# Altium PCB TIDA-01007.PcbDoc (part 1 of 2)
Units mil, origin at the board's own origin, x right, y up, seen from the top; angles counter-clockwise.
Board outline 4950 x 3450 mil, 2 copper layers (Top Layer, Bottom Layer), stack 62 mil thick; 82 components, 45 nets, 235 pads, 1732 vias.
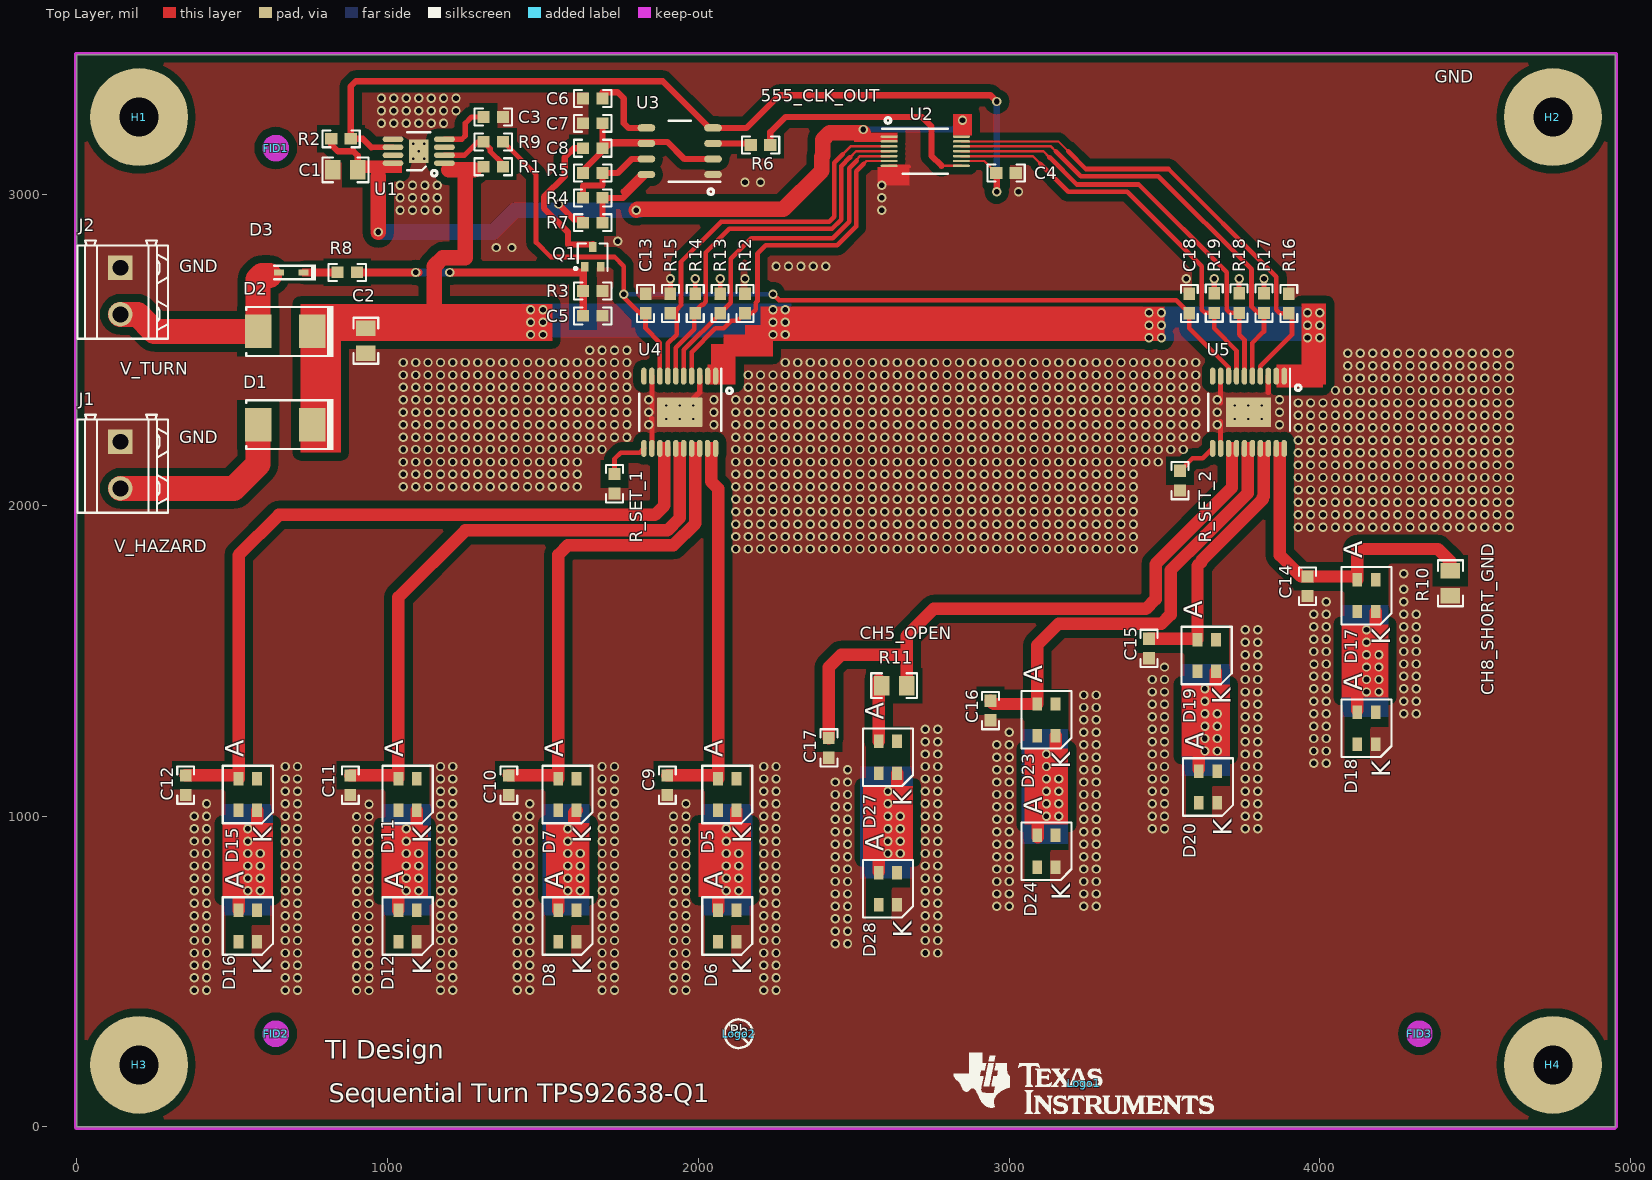
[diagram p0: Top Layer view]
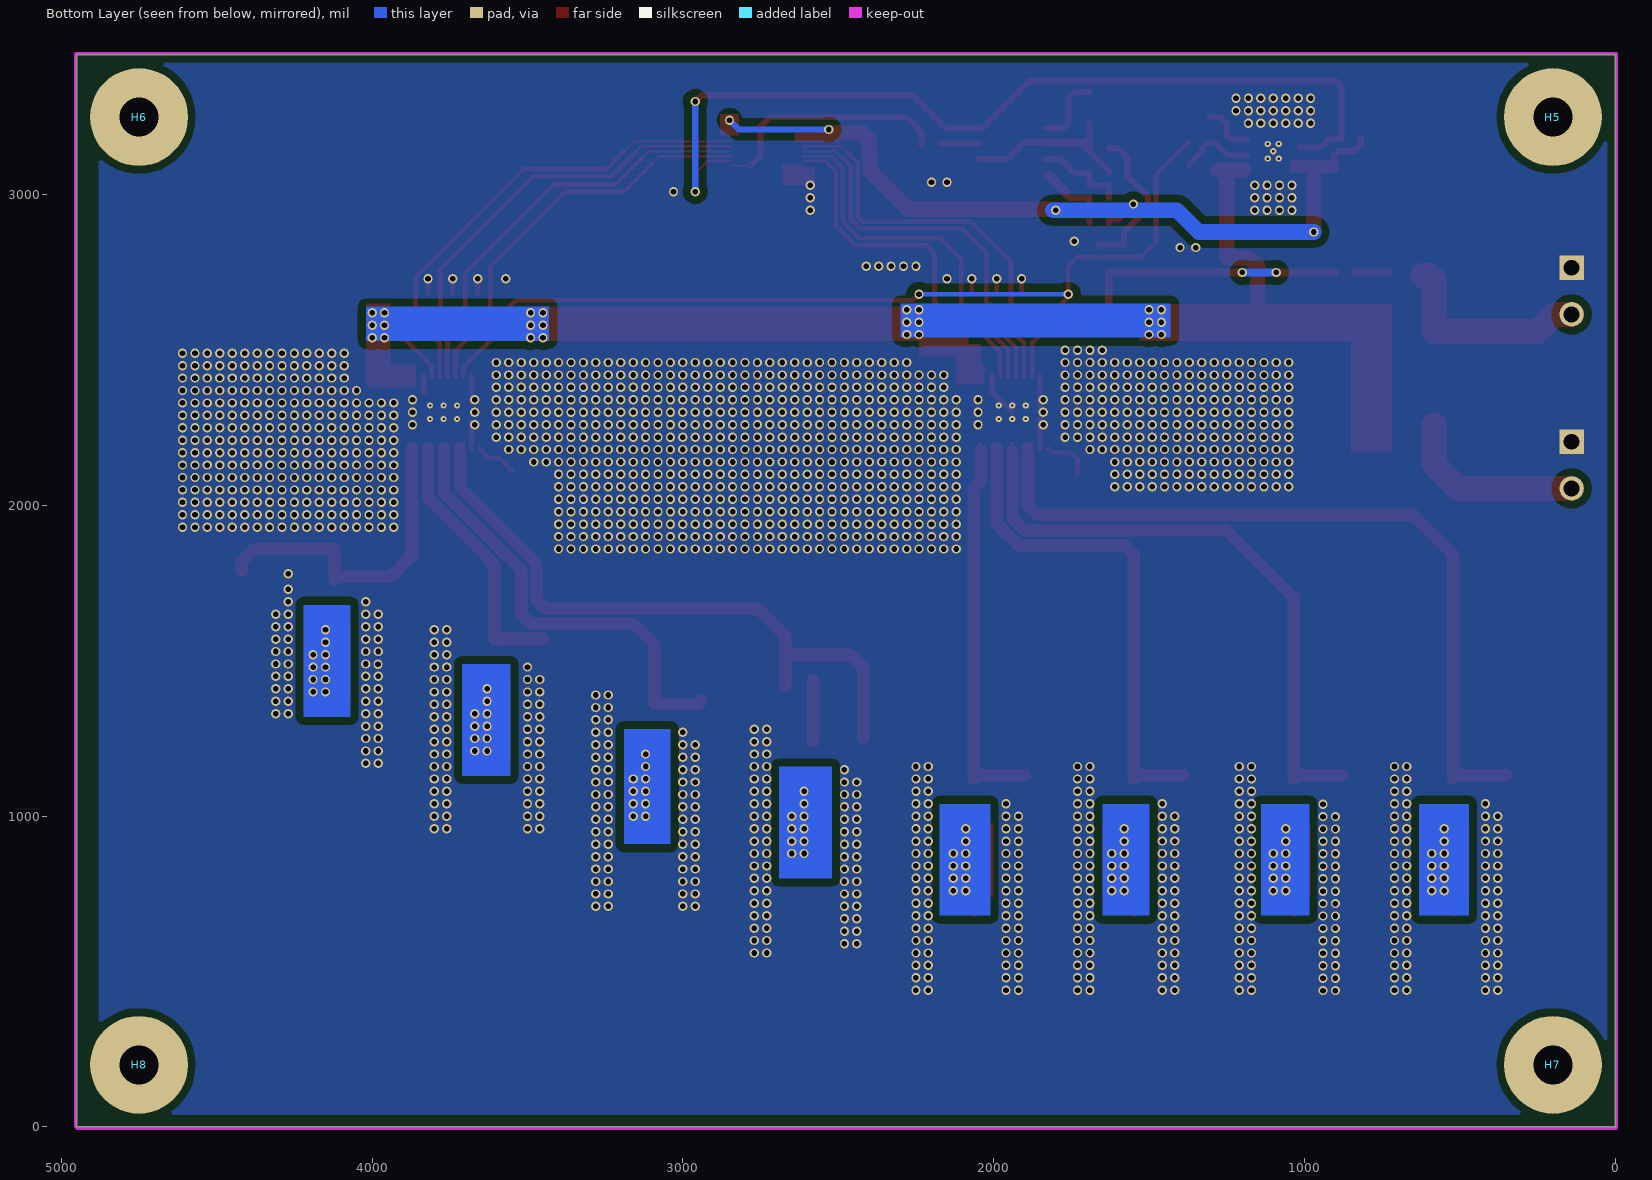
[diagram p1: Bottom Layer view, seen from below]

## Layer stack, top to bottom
Top Solder: solder mask 0.4, Solder Resist, Dk 3.5
Top Layer: signal copper 1.4
Dielectric1: core 59.2, FR-4, Dk 4.8
Bottom Layer: signal copper 1.4
Bottom Solder: solder mask 0.4, Solder Resist, Dk 3.5

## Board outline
0,0 4950,0 4950,3450 0,3450

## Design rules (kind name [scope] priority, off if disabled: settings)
AcuteAngle [All] p1: minimum=4.50000000000000E+0001 checktracksonly=FALSE
AssemblyTestPointUsage [All] p1: valid=2
Clearance Clearance_Keepouts [((IsTrack Or IsArc) And Not InPoly) And IsFree and IsKeepOut vs ((IsTrack Or IsArc) And Not InPoly) And IsFree and IsKeepOut] p1: gap=0
Clearance Clearance_BoardEdge_MountingHoles [OnCopper and InComponentClass('Mounting Holes') vs IsKeepOut] p2: gap=40
Clearance Clearance_BoardEdge_Poly [OnCopper and InPoly vs IsKeepOut] p3: gap=25
Clearance Clearance_BoardEdge [OnCopper and Not InComponentClass('Logo') and not InComponentClass('FiducialMark') and not InRegion(1000,500,4000,800) and Not IsKeepout vs IsKeepOut] p4: gap=75
Clearance Clearance_Poly [InPolygon] p5: gap=25
Clearance [All] p6: gap=7.87
ComponentClearance ComponentClearance_MountingHoles_FiducialMarks [InComponentClass('Mounting Holes') vs InComponentClass('FiducialMark')] p1: gap=50 collisioncheckmode=3 verticalgap=10 showdistances=FALSE
ComponentClearance ComponentClearance_Shunt [InComponentClass('Header') vs InComponentClass('Shunt')] p2: gap=0 collisioncheckmode=3 verticalgap=0 showdistances=FALSE
ComponentClearance ComponentClearance_Logo [InComponentClass('Logo')] p3: gap=50 collisioncheckmode=3 verticalgap=10 showdistances=FALSE
ComponentClearance ComponentClearance_ScrewToNut [(HasFootprint('NY PMS 440 0025 PH')) vs (HasFootprint('Keystone_1902C'))] p4: gap=5 collisioncheckmode=3 verticalgap=10 showdistances=FALSE
ComponentClearance ComponentClearance_MountingHoles [InComponentClass('Mounting Holes')] p5: gap=250 collisioncheckmode=3 verticalgap=100000 showdistances=FALSE
ComponentClearance ComponentClearance_SmallPassives [HasFootprint('0201*') or HasFootprint('0402*') or HasFootprint('0508') or HasFootprint('0603*') or HasFootprint('0612') or HasFootprint('0805*') or HasFootprint('0815*') or HasFootprint('0830*') or HasFootprint('1206*') or HasFootprint('1210*') or HasFootprint('1808*') or HasFootprint('1812*') or HasFootprint('1825*') or HasFootprint('2010*') or HasFootprint('2220*') or HasFootprint('2225*') or HasFootprint('2512*') or HasFootprint('2728*') or HasFootprint('3518*') vs HasFootprint('0201*') or HasFootprint('0402*') or HasFootprint('0508') or HasFootprint('0603*') or HasFootprint('0612') or HasFootprint('0805*') or HasFootprint('0815*') or HasFootprint('0830*') or HasFootprint('1206*') or HasFootprint('1210*') or HasFootprint('1808*') or HasFootprint('1812*') or HasFootprint('1825*') or HasFootprint('2010*') or HasFootprint('2220*') or HasFootprint('2225*') or HasFootprint('2512*') or HasFootprint('2728*') or HasFootprint('3518*')] p6: gap=20 collisioncheckmode=3 verticalgap=10 showdistances=FALSE
ComponentClearance ComponentClearance_THtoSMT [IsThruComponent vs IsSMTComponent] p7: gap=100 collisioncheckmode=3 verticalgap=30 showdistances=FALSE
ComponentClearance ComponentClearance_THtoTH [IsThruComponent vs IsThruComponent] p8: gap=118.11 collisioncheckmode=3 verticalgap=30 showdistances=FALSE
ComponentClearance [All] p9: gap=40 collisioncheckmode=3 verticalgap=10 showdistances=FALSE
DiffPairsRouting [All] p1: maxlimit=100 minlimit=10 mostfreqgap=10 toplayer_minwidth=15 toplayer_maxwidth=15 toplayer_prefwidth=15 bottomlayer_minwidth=15 bottomlayer_maxwidth=15 bottomlayer_prefwidth=15 maxuncoupledlength=1000
FabricationTestPointUsage TestPointUsage [All] p1: valid=2 allowmultiple=FALSE
FabricationTestpoint Testpoint [All] p1: side=3 testpointundercomponent=TRUE minsize=40 maxsize=100 preferedsize=60 minholesize=0 maxholesize=40 preferedholesize=32 testpointgrid=1 allowsidetop=TRUE allowsidebottom=TRUE usegrid=TRUE gridtolerance=0.01
FanoutControl Fanout_LCC [IsLCC] p1: bgadir=Out bgaviamode=Centered fanoutstyle=Auto fanoutdirection=Alternating viagrid=1 // Fanout_LCC (Default Rule)
FanoutControl Fanout_BGA [IsBGA] p2: bgadir=Out bgaviamode=Centered fanoutstyle=Auto fanoutdirection=Alternating viagrid=1 // Fanout_BGA (Default Rule)
FanoutControl Fanout_Default [All] p4: bgadir=Out bgaviamode=Centered fanoutstyle=Auto fanoutdirection=Alternating viagrid=1 // Fanout_Default (Default Rule)
FanoutControl Fanout_Small [(CompPinCount < 5)] p5: bgadir=Out bgaviamode=Centered fanoutstyle=Auto fanoutdirection=OutThenIn viagrid=1 // Fanout_Small (Default Rule)
HoleSize [All] p1: absolutevalues=TRUE maxlimit=251 minlimit=6 maxpercent=80.000 minpercent=20.000
MinimumAnnularRing MinimumAnnularRing_ThermalPadVias [IsVia and InAnyComponent] p1: minimumring=5.91
MinimumAnnularRing [All] p2: minimumring=9
MinimumSolderMaskSliver MinimumSolderMaskSliver_Logo [InComponentClass('Logo') vs InComponentClass('Logo')] p1: minsoldermaskwidth=0.7
MinimumSolderMaskSliver [All] p2: minsoldermaskwidth=3.94
PlaneClearance [All] p1: clearance=10
PlaneConnect [All] p1: planeconnectstyle=Relief reliefexpansion=10 reliefentries=4 reliefconductorwidth=10 reliefairgap=10
PolygonConnect [All] p1: connectstyle=Direct reliefconductorwidth=10 reliefentries=4 polygonreliefangle="90 Angle" airgapwidth=10
RoutingVias ThermalPadVias [IsVia and InAnyComponent] p1: holewidth=7.87 width=19.68 viastyle="Through Hole" minholewidth=7.87 minwidth=19.68 maxholewidth=12.99 maxwidth=23.62
RoutingVias [All] p2: holewidth=16 width=34 viastyle="Through Hole" minholewidth=7.87 minwidth=26 maxholewidth=40 maxwidth=65
SilkToBoardRegionClearance [Not ((IsComment or IsDesignator) And (Hide <> 'False')) and not InRegion(1000,500,4000,800)] p1:
SilkToSilkClearance SilkToSilkClearance_Pb-FreeLogo [(HasFootprint('Pb-Free_Overlay_Medium') OR HasFootprint('Pb-Free_Overlay_Small')) vs (HasFootprint('Pb-Free_Overlay_Medium') OR HasFootprint('Pb-Free_Overlay_Small'))] p1: silktosilkclearance=0
SilkToSilkClearance [All] p2: silktosilkclearance=4
SilkToSolderMaskClearance "Silk to Solder Mask Opening" [All] p1: minsilkscreentomaskgap=0 clearancetoexposedcopper=FALSE
SolderMaskExpansion [All] p1: expansion=1.97
UnpouredPolygon [All] p1: allowunpoured=FALSE
Width [All] p1: maxlimit=100 minlimit=6 preferedwidth=10 checkconnectedcopper=TRUE
13 further rules are at their usual default settings.

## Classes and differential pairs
component class TIDA-01007_CoverSheet: C1 C2 C3 C4 C5 C6 C7 C8 C9 C10 C11 C12 C13 C14 C15 C16 C17 C18 D1 D2 D3 D5 D6 D7 D8 D11 D12 D15 D16 D17 D18 D19 D20 D23 D24 D27 D28 J1 J2 P1 P2 PWM2 PWM8 Q1 R1 R2 R3 R4 R5 R6 R7 R8 R9 R10 R11 R12 R13 R14 R15 R16 R17 R18 R19 R_SET_1 R_SET_2 U1 U2 U3 U4 U5
component class "Mounting Holes": H1 H2 H3 H4
component class Logo: Logo1
component class TID_Hardware: FID1 FID2 FID3 H1 H2 H3 H4 H5 H6 H7 H8 Logo1 Logo2 ZZ1 ZZ2 ZZ3
component class FiducialMark: FID1 FID2 FID3
component class AssemblyNote: ZZ1 ZZ2 ZZ3

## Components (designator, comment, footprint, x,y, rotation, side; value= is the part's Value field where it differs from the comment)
C1 "0805YD225KAT2A" 0805_HV 864.02,3080 r180 top
C2 "08055C105KAT2A" 0805_HV 930,2530 r270 top
C3 "06033C101KAT2A" 0603 1340,3250 r0 top
C4 "CL10B103KB8NCNC" 0603 2990,3070 r0 top
C5 "CL10B103KB8NCNC" 0603 1660,2610 r0 top
C6 "CL10B103KB8NCNC" 0603 1659.91,3309.73 r180 top
C7 "C0603C222K5RAC" 0603 1659.91,3229.73 r180 top
C8 "0603YC104JAT2A" 0603 1659.91,3149.73 r180 top
C9 "C0603C103K5RACTU" 0603 1900,1100 r270 top
C10 "C0603C103K5RACTU" 0603 1390,1100 r270 top
C11 "C0603C103K5RACTU" 0603 880,1100 r270 top
C12 "C0603C103K5RACTU" 0603 350,1100 r270 top
C13 "C0603X102K5RACTU" 0603 1830,2650 r90 top
C14 "C0603C103K5RACTU" 0603 3960,1740 r270 top
C15 "C0603C103K5RACTU" 0603 3450,1540 r270 top
C16 "C0603C103K5RACTU" 0603 2940,1340 r270 top
C17 "C0603C103K5RACTU" 0603 2420,1220 r270 top
C18 "C0603X102K5RACTU" 0603 3580,2650 r90 top
D1 "B340LB-13-F" SMB 670,2260 r180 top
D2 "B340LB-13-F" SMB 670,2560 r180 top
D3 "1N4148WT" Fairchild_SOD-523F 690,2750 r180 top
D5 "LA E63F-EBGA-24-1-Z" LED_PowerTOPLED_GF_lens 2092.86,1070 r90 top
D6 "LA E63F-EBGA-24-1-Z" LED_PowerTOPLED_GF_lens 2092.86,647 r90 top
D7 "LA E63F-EBGA-24-1-Z" LED_PowerTOPLED_GF_lens 1578.57,1070 r90 top
D8 "LA E63F-EBGA-24-1-Z" LED_PowerTOPLED_GF_lens 1578.57,647 r90 top
D11 "LA E63F-EBGA-24-1-Z" LED_PowerTOPLED_GF_lens 1064.29,1070 r90 top
D12 "LA E63F-EBGA-24-1-Z" LED_PowerTOPLED_GF_lens 1064.29,647 r90 top
D15 "LA E63F-EBGA-24-1-Z" LED_PowerTOPLED_GF_lens 550,1070 r90 top
D16 "LA E63F-EBGA-24-1-Z" LED_PowerTOPLED_GF_lens 550,647 r90 top
D17 "LA E63F-EBGA-24-1-Z" LED_PowerTOPLED_GF_lens 4150,1710 r90 top
D18 "LA E63F-EBGA-24-1-Z" LED_PowerTOPLED_GF_lens 4150,1283 r90 top
D19 "LA E63F-EBGA-24-1-Z" LED_PowerTOPLED_GF_lens 3635.71,1517.13 r90 top
D20 "LA E63F-EBGA-24-1-Z" LED_PowerTOPLED_GF_lens 3640,1094.13 r90 top
D23 "LA E63F-EBGA-24-1-Z" LED_PowerTOPLED_GF_lens 3120,1310 r90 top
D24 "LA E63F-EBGA-24-1-Z" LED_PowerTOPLED_GF_lens 3120,887 r90 top
D27 "LA E63F-EBGA-24-1-Z" LED_PowerTOPLED_GF_lens 2610,1190 r90 top
D28 "LA E63F-EBGA-24-1-Z" LED_PowerTOPLED_GF_lens 2610,767 r90 top
FID1 "Fiducial" Fiducial10-20 640,3150 r0 top
FID2 "Fiducial" Fiducial10-20 640,300 r0 top
FID3 "Fiducial" Fiducial10-20 4320,300 r0 top
H1 "NY PMS 440 0025 PH" "NY PMS 440 0025 PH" 200,3250 r0 top locked
H2 "NY PMS 440 0025 PH" "NY PMS 440 0025 PH" 4750,3250 r0 top locked
H3 "NY PMS 440 0025 PH" "NY PMS 440 0025 PH" 200,200 r0 top locked
H4 "NY PMS 440 0025 PH" "NY PMS 440 0025 PH" 4750,200 r0 top locked
H5 "1902C" Keystone_1902C 200,3250 r180 bottom locked
H6 "1902C" Keystone_1902C 4750,3250 r180 bottom locked
H7 "1902C" Keystone_1902C 200,200 r180 bottom locked
H8 "1902C" Keystone_1902C 4750,200 r180 bottom locked
J1 "691214310002" Wurth_691214310002 140,2130 r270 top
J2 "691214310002" Wurth_691214310002 140,2690 r270 top
Logo1 "Texas Instruments" TI_Stacked_Overlay_Small 3240,140 r0 top
Logo2 "Pb-Free Symbol" Pb-Free_Overlay_Small 2130,300 r0 top
Q1 "2N7002KW" SOT-323 1660,2800 r90 top
R1 "RG1608P-103-B-T5" 0603 1340,3090 r0 top
R2 "RG1608P-103-B-T5" 0603 850,3180 r180 top
R3 "CRCW060310K0FKEA" 0603 1660,2690 r0 top
R4 "CRCW060310K0FKEA" 0603 1659.91,2989.73 r180 top
R5 "CRCW0603150KFKEA" 0603 1659.91,3069.73 r0 top
R6 "CRCW06030000Z0EA" 0603 2200,3160 r180 top
R7 "CRCW06030000Z0EA" 0603 1660,2910 r0 top
R8 "CRCW060310K0FKEA" 0603 870,2750 r0 top
R9 "CRCW06030000Z0EA" 0603 1340,3170 r0 top
R10 "CRCW08050000Z0EA" 0805_HV 4420,1750 r270 top
R11 "CRCW08050000Z0EA" 0805_HV 2630,1420 r180 top
R12 "RG1608P-103-B-T5" 0603 2150,2650 r90 top
R13 "RG1608P-103-B-T5" 0603 2070,2650 r90 top
R14 "RG1608P-103-B-T5" 0603 1990,2650 r90 top
R15 "RG1608P-103-B-T5" 0603 1910,2650 r90 top
R16 "RG1608P-103-B-T5" 0603 3900,2650 r90 top
R17 "RG1608P-103-B-T5" 0603 3820,2651.3 r90 top
R18 "RG1608P-103-B-T5" 0603 3740,2651.3 r90 top
R19 "RG1608P-103-B-T5" 0603 3660,2651.3 r90 top
R_SET_1 "CRCW060310K0FKEA" 0603 1730,2070 r270 top
R_SET_2 "CRCW060310K0FKEA" 0603 3550,2080 r270 top
U1 "TPS7A6650QDGNRQ1" DGN0008D_N 1100,3140 r180 top
U2 "SN74LV164ADGVR" DGV0014A_N 2730,3140 r0 top
U3 "TLC555QDRQ1" D0008A_N 1940,3140 r180 top
U4 "TPS92638QPWPRQ1" PWP0020D_N 1940,2300 r270 top
U5 "TPS92638QPWPRQ1" PWP0020D_N 3770,2300 r270 top
ZZ1 "These assemblies are ESD sensitive, ESD precautions shall be observed." AssemblyNote 185,3829.11 r0 top
ZZ2 "These assemblies must be clean and free from flux and all contaminants. Use of no clean flux is not acceptable." AssemblyNote 185,3740.56 r0 top
ZZ3 "These assemblies must comply with workmanship standards IPC-A-610 Class 2, unless otherwise specified." AssemblyNote 185,3652 r0 top

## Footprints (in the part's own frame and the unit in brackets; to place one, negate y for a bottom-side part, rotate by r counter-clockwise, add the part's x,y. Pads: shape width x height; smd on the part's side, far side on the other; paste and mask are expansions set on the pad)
0603 [mm] "0603 from SM-752 data"
  rect 1x0.95 smd: 1(-0.8,0) 2(0.8,0)
  silkscreen extent -1.52,-0.69 1.52,0.69, body extent -0.87,-0.47 0.87,0.47, height 0.85
0805_HV [mil] "0805 with 30mil clearance between pads"
  rect 50x63 smd: 1(-40,0) 2(40,0)
  silkscreen extent -74,-40 74,40, body extent -43,-29 43,29, height 43
AssemblyNote [mil] "Assembly Note"
D0008A_N [mm] "SOIC, 8-Leads, Body 4.9x3.9mm, Pitch 1.27mm, IPC Medium Density"
  oval 1.45x0.6 smd: 1(-2.725,1.905) 2(-2.725,0.635) 3(-2.725,-0.635) 4(-2.725,-1.905) 5(2.725,-1.905) 6(2.725,-0.635) 7(2.725,0.635) 8(2.725,1.905)
  silkscreen extent -3.3,-2.5 0.9,2.5, body extent -3,-2.45 3,2.45, height 1.63
DGN0008D_N [mm] "TSOP, 8-Leads, Body 3x3mm, Pitch 0.65mm, Thermal Pad 1.89x1.57mm, IPC Medium Density"
  oval 1.7x0.45 smd: 1(-2.1,0.975) 2(-2.1,0.325) 3(-2.1,-0.325) 4(-2.1,-0.975) 5(2.1,-0.975) 6(2.1,-0.325) 7(2.1,0.325) 8(2.1,0.975)
  rect 1.57x1.89 smd: 9(0,0)
  silkscreen extent -0.95,-1.55 0.95,1.55, body extent -2.45,-1.5 2.45,1.5, height 0.94
DGV0014A_N [mm] "TSSOP, 14-Leads, Body 3.60x4.40mm, Pitch 0.40mm, IPC Medium Density"
  oval 1.4x0.2 smd: 1(-2.95,1.2) 2(-2.95,0.8) 3(-2.95,0.4) 4(-2.95,0) 5(-2.95,-0.4) 6(-2.95,-0.8) 7(-2.95,-1.2) 8(2.95,-1.2) 9(2.95,-0.8) 10(2.95,-0.4) 11(2.95,0) 12(2.95,0.4) 13(2.95,0.8) 14(2.95,1.2)
  silkscreen extent -3.52,-1.85 1.85,1.85, body extent -3.21,-1.8 3.21,1.8, height 1.2
Fairchild_SOD-523F [mm] "SMD, 2-Leads, Body 1.2x0.8mm"
  rect 0.8x0.5 smd: 1(-1,0) 2(1,0)
  silkscreen extent -2.03,-0.65 1.4,0.65, body extent -0.65,-0.45 0.65,0.45, height 0.7
Fiducial10-20 [mm]
  round 1 smd mask+0.5: 1(0,0)
  Top Layer keep-out circle w1.178: c0,0 r0.5
Keystone_1902C [mil] "Hex Standoff, 4-40 threaded, nylon"
  body extent -145,-126 146,126, height 501
LED_PowerTOPLED_GF_lens [mm] "Osram recommended land pattern,  \"LA_LO_LR_LS_LY_E6SF_Pb_free.pdf\", dated 2008-11-27"
  rect 1.1x0.8 smd: 1(-1.3,0.75) 2(-1.3,-0.75) 3(1.3,-0.75) 4(1.3,0.75)
  silkscreen extent -2.35,-2.05 2.35,2.05, body extent -1.7,-1.5 1.7,1.5, height 3.37
"NY PMS 440 0025 PH" [mm] "4-40 nylon screw and mounting hole"
  round 8 hole 3.2: 1(0,0)
  body extent -3.3,-3.3 3.3,3.3, height 2.69
Pb-Free_Overlay_Small [mil]
  silkscreen extent -46,-46 46,46
PWP0020D_N [mm] "SOP, 20-Leads, Body 6.4x4.4mm, Pitch 0.65mm, Thermal Pad 2x3mm, IPC Medium Density"
  rrect100% 1.4x0.45 smd: 1(-2.95,2.925) 2(-2.95,2.275) 3(-2.95,1.625) 4(-2.95,0.975) 5(-2.95,0.325) 6(-2.95,-0.325) 7(-2.95,-0.975) 8(-2.95,-1.625) 9(-2.95,-2.275) 10(-2.95,-2.925) 11(2.95,-2.925) 12(2.95,-2.275) 13(2.95,-1.625) 14(2.95,-0.975) 15(2.95,-0.325) 16(2.95,0.325) 17(2.95,0.975) 18(2.95,1.625) 19(2.95,2.275) 20(2.95,2.925)
  rrect4% 2.4x3.7 smd: 21(0,0)
  silkscreen extent -3.55,-3.3 1.5,3.4, body extent -3.21,-3.25 3.21,3.25, height 1
SMB [mil] "Molded Diode, 2-Leads, Body 5.4x3.6mm, IPC Medium Density, based on OnSemi component dimensions"
  rect 85x107.99 smd: 1(-87.01,0) 2(87.01,0)
  silkscreen extent -155,-82 125,82, body extent -106,-71 106,71, height 91
SOT-323 [mm] "Zetex recommended land pattern.  March 2007"
  rect 0.8x0.6 smd: 1(-0.8,0.65) 2(-0.8,-0.65) 3(0.8,0)
  silkscreen extent -1.14,-1.22 1.09,1.49, body extent -1.13,-1.13 1.12,1.12, height 1.13
TI_Stacked_Overlay_Small [mil]
  silkscreen extent -418,-98 418,98
Wurth_691214310002 [mm] "WE"
  rect 2x2 hole 1.3: 1(-1.905,0)
  round 2 hole 1.3: 2(1.905,0)
  silkscreen extent -4.12,-3.5 3.9,3.9, body extent -4.12,-3.5 3.9,3.9, height 8.52

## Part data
C1: "CAP, CERM, 2.2 µF, 16 V, +/- 10%, X5R, 0805"
C2: "CAP, CERM, 1 µF, 50 V, +/- 10%, X7R, 0805"
C3: "CAP, CERM, 100 pF, 25 V, +/- 10%, X7R, 0603"
C4 C5 C6 C9 C10 C11 C12 C14 C15 C16 C17: "CAP, CERM, 0.01 µF, 50 V, +/- 10%, X7R, 0603"
C7: "CAP, CERM, 2200 pF, 50 V, +/- 10%, X7R, 0603"
C8: "CAP, CERM, 0.1 µF, 16 V, +/- 5%, X7R, 0603"
C13 C18: "CAP, CERM, 1000 pF, 50 V, +/- 10%, X7R, 0603"
D1 D2: "Diode, Schottky, 40V, 3A, SMB"
D3: "Diode, Switching, 75 V, 0.3 A, SMD, 2-Leads, Body 1.2x0.8mm"
D5 D6 D7 D8 D11 D12 D15 D16 D17 D18 D19 D20 D23 D24 D27 D28: "LED, Amber, SMD"
FID1 FID2 FID3: "Fiducial mark.  There is nothing to buy or mount."
H1 H2 H3 H4: "Machine Screw, Round, #4-40 x 1/4, Nylon, Philips panhead"
H5 H6 H7 H8: "Standoff, Hex, 0.5\"L #4-40 Nylon"
J1 J2: "Terminal Block, 2x1, 3.81mm, 24-16 AWG, 10A, 300VAC, TH"
Logo1: library part TI_Logo, "Texas Instrument Corporate Signature"
Logo2: library part Pb-Free
Q1: "MOSFET, N-CH, 60 V, 0.31 A, SOT-323"
R1 R2 R12 R13 R14 R15 R16 R17 R18 R19: "RES, 10.0 k, 0.1%, 0.1 W, 0603"
R3 R4 R8 R_SET_1 R_SET_2: "RES, 10.0k ohm, 1%, 0.1W, 0603"
R5: "RES, 150 k, 1%, 0.1 W, 0603"
R6 R7 R9: "RES, 0, 5%, 0.1 W, 0603"
R10 R11: "RES, 0, 5%, 0.125 W, 0805"
U1: "High-Voltage Ultralow-Iq Low-Dropout Regulator, DGN0008D"
U2: "8-BIT PARALLEL-OUT SERIAL SHIFT REGISTERS, DGV0014A"
U3: "LinCMOS Timer, D0008A"
U4 U5: "Eight-Channel Linear LED Driver with PWM Dimming, PWP0020D"
ZZ1 ZZ2 ZZ3: library part AssemblyNote

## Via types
v1: diameter 30, hole 18, Top Layer to Bottom Layer, 1715 vias
v2: diameter 19.68, hole 7.87, Top Layer to Bottom Layer, 17 vias

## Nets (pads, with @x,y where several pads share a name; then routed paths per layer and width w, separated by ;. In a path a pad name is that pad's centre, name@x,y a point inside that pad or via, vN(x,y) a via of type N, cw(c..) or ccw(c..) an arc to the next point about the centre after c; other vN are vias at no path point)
CLK_OUT: R6.2 U3.3 | length 121.2
  Top Layer w20: U3.3@2047.28,3165 R6.2@2168.5,3165
FAULT_BUS: C13.1 C18.1 R9.2 U4.8 U5.8 | length 3194.3
  Top Layer w15: R9.2@1371.5,3170 1477.63,3063.87 1477.63,2846.49 1524.49,2799.63 1730.37,2799.63 1760,2770 v1(1760,2680) 1760,2670 1811.5,2618.5 C13.1@1830,2618.5 1830,2570 1876.02,2523.98 U4.8@1876.02,2416.14 ; v1(2240,2680) 2259.63,2660.37 3538.13,2660.37 C18.1@3580,2618.5 3580,2570 3706.02,2443.98 U5.8@3706.02,2416.14
  Bottom Layer w15: v1(1760,2680) v1(2240,2680)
